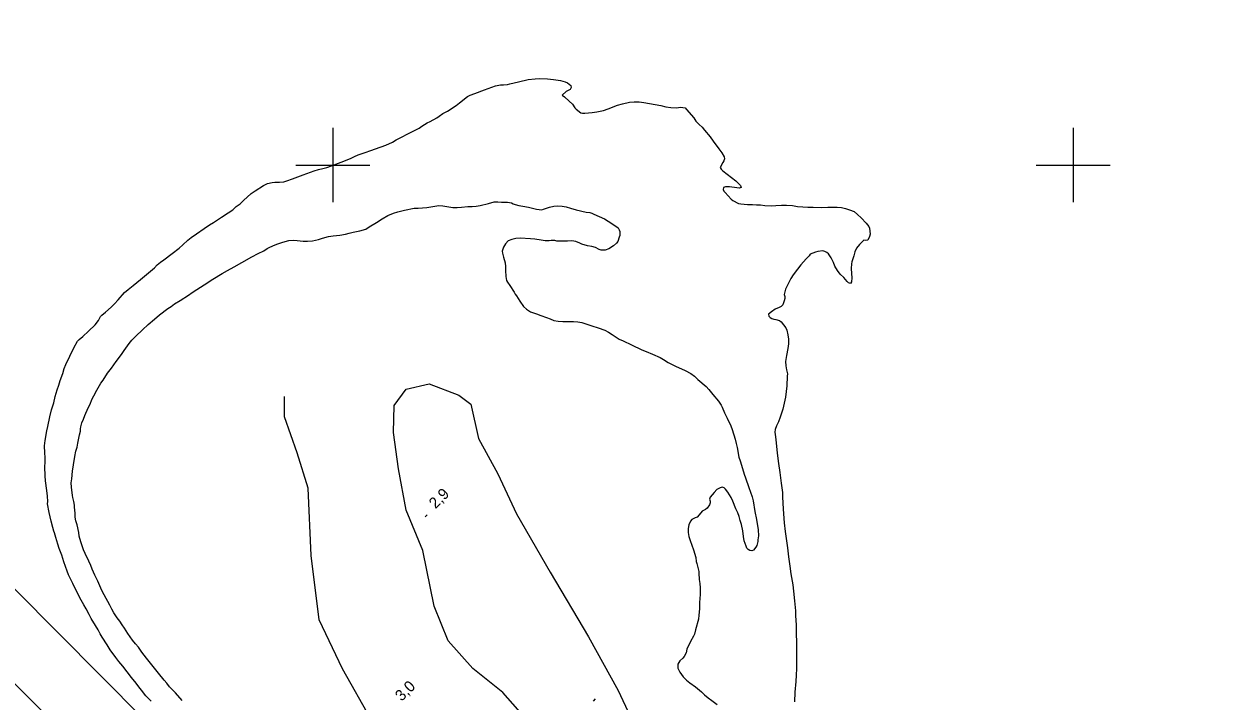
# Model space of a CAD drawing. Extents: x 381879 to 384696, y 5564785 to 5567594.
# Drawn here: x 382116.5 to 382438.6, y 5565455.1 to 5565638.1 of the extents above; entities that cross this region are included whole.
import ezdxf

# ---------------------------------------------------------------- set-up
doc = ezdxf.new("R2010")
doc.units = 0
for name, color, linetype in [('Niveau 2', 7, 'Continuous'), ('Niveau 22', 7, 'Continuous'), ('Niveau 3', 7, 'Continuous'), ('Niveau 4', 7, 'Continuous'), ('Niveau 60', 7, 'Continuous'), ('Niveau 61', 7, 'Continuous')]:
    doc.layers.add(name, color=color, linetype=linetype)

msp = doc.modelspace()

# ---------------------------------------------------------------- linework, layer by layer
at = {"layer": 'Niveau 2'}
for points in [[(382130.91, 5565523.8), (382131.1, 5565524.86), (382131.56, 5565527.09), (382131.86, 5565528.1), (382131.82, 5565528.68), (382131.89, 5565529.25), (382132.14, 5565530.3), (382132.62, 5565531.32), (382133.01, 5565532.34), (382133.85, 5565534.4), (382134.4, 5565535.42), (382134.86, 5565536.6), (382135.45, 5565537.61), (382136.27, 5565539.19), (382137.29, 5565541.05), (382137.9, 5565541.89), (382139.15, 5565543.73), (382140.19, 5565545.12), (382141.49, 5565546.92), (382142.92, 5565548.79), (382143.64, 5565549.9), (382144.94, 5565551.78), (382145.65, 5565552.63), (382146.81, 5565553.8), (382148.54, 5565555.47), (382150.09, 5565556.91), (382151.77, 5565558.39), (382153.2, 5565559.51), (382155.4, 5565561.25), (382156.32, 5565561.81), (382157.25, 5565562.48), (382158.71, 5565563.36), (382161.03, 5565564.81), (382161.97, 5565565.52), (382163.25, 5565566.39), (382165.2, 5565567.66), (382167.54, 5565569.12), (382170.08, 5565570.71), (382171.52, 5565571.54), (382173.36, 5565572.53), (382175.42, 5565573.7), (382178.13, 5565575.22), (382179.82, 5565576.11), (382181.31, 5565576.83), (382182.22, 5565577.46), (382182.74, 5565577.74), (382183.74, 5565578.19), (382184.83, 5565578.58), (382186.52, 5565579.13), (382188.07, 5565579.58), (382189.28, 5565579.67), (382190.34, 5565579.61), (382191.98, 5565579.43), (382193.16, 5565579.39), (382194.46, 5565579.5), (382196.1, 5565579.85), (382197.19, 5565580.25), (382198.83, 5565580.72), (382200.08, 5565580.9), (382201.86, 5565581.06), (382203.36, 5565581.31), (382204.37, 5565581.61), (382205.48, 5565581.84), (382207.3, 5565582.17), (382208.87, 5565582.67), (382209.84, 5565583.27), (382211.82, 5565584.43), (382213.34, 5565585.43), (382214.87, 5565586.32), (382216.38, 5565587.03), (382217.54, 5565587.35), (382219.31, 5565587.77), (382221.93, 5565588.31), (382223.04, 5565588.34), (382225.35, 5565588.49), (382226.45, 5565588.71), (382228.62, 5565589.04), (382229.72, 5565588.99), (382230.82, 5565588.76), (382232.43, 5565588.52), (382233.59, 5565588.52), (382234.7, 5565588.65), (382236.46, 5565588.81), (382237.58, 5565588.8), (382238.72, 5565588.88), (382239.76, 5565589.1), (382241.99, 5565589.62), (382243.57, 5565590.07), (382244.56, 5565590.09), (382245.58, 5565589.98), (382247.21, 5565589.97), (382248.21, 5565589.77), (382248.67, 5565589.52), (382249.21, 5565589.34), (382250.25, 5565589.08), (382251.31, 5565588.91), (382252.87, 5565588.57), (382254.96, 5565588.07), (382256.43, 5565587.91), (382256.92, 5565588.09), (382258.55, 5565588.62)], [(382258.55, 5565588.62), (382259.68, 5565588.88), (382260.76, 5565588.94), (382261.89, 5565588.88), (382263.01, 5565588.71), (382264.19, 5565588.33), (382265.71, 5565587.9), (382268.4, 5565587.23), (382269.45, 5565587.13), (382269.96, 5565586.98), (382270.45, 5565586.73), (382271.97, 5565586.13), (382273.39, 5565585.44), (382274.34, 5565584.85), (382276.15, 5565583.65), (382277.05, 5565582.98), (382277.32, 5565582.52), (382277.49, 5565581.99), (382277.52, 5565580.97), (382277.37, 5565580.46), (382276.97, 5565579.36), (382276.58, 5565578.86), (382275.81, 5565578.19), (382274.54, 5565577.34), (382273.51, 5565576.97), (382272.5, 5565576.98), (382271.94, 5565577.18), (382270.95, 5565577.67), (382269.92, 5565577.98), (382268.76, 5565578.17), (382267.23, 5565578.57), (382266.73, 5565578.89), (382265.61, 5565579.34), (382264.52, 5565579.47), (382263.4, 5565579.43), (382260.47, 5565579.42), (382259.97, 5565579.62), (382258.98, 5565579.62), (382258.45, 5565579.54), (382257.38, 5565579.52), (382256.26, 5565579.67), (382254.51, 5565579.99), (382253.34, 5565580.07), (382250.55, 5565580.24), (382249.44, 5565580.15), (382248.35, 5565579.86), (382247.32, 5565579.48), (382246.67, 5565578.72), (382246.1, 5565577.76), (382245.74, 5565576.73), (382245.81, 5565576.21), (382246.07, 5565575.12), (382246.51, 5565573.61), (382246.63, 5565572.55), (382246.59, 5565571.53), (382246.68, 5565569.84), (382246.92, 5565568.83), (382247.14, 5565568.38), (382247.79, 5565567.46), (382249, 5565565.68), (382249.22, 5565565.13), (382249.58, 5565564.65), (382250.48, 5565563.19), (382251.49, 5565561.73), (382252.31, 5565561.01), (382253.34, 5565560.37), (382253.92, 5565560.15), (382255.02, 5565559.81), (382256.14, 5565559.34), (382257.74, 5565558.81), (382258.71, 5565558.4), (382259.71, 5565558.01), (382260.88, 5565557.84), (382262.07, 5565557.74), (382263.83, 5565557.68), (382264.99, 5565557.73), (382266.12, 5565557.64), (382267.24, 5565557.45), (382268.3, 5565557.11), (382269.94, 5565556.51), (382271.66, 5565555.98), (382273.42, 5565555.37), (382274.47, 5565554.83), (382275.4, 5565554.2), (382277.37, 5565552.93), (382278.4, 5565552.46), (382280.64, 5565551.4), (382283.46, 5565550.06), (382284.64, 5565549.62), (382286.32, 5565548.92), (382288.45, 5565547.99), (382289.33, 5565547.48), (382290.61, 5565546.65), (382291.64, 5565546.09), (382292.59, 5565545.67), (382295.19, 5565544.46), (382296.7, 5565543.67), (382297.67, 5565542.94), (382298.6, 5565542.09), (382300.8, 5565540.12), (382301.54, 5565539.33)], [(382301.54, 5565539.33), (382302.62, 5565538), (382304.17, 5565536.17), (382304.89, 5565535.15), (382305.12, 5565534.58), (382305.8, 5565533.07), (382306.51, 5565531.62), (382307.46, 5565529.53), (382307.83, 5565528.51), (382308.69, 5565525.92), (382308.98, 5565524.79), (382309.17, 5565523.72), (382309.69, 5565521.09), (382309.98, 5565520.11), (382310.64, 5565518.04), (382311.07, 5565516.49), (382311.44, 5565515.46), (382312.38, 5565512.89), (382313.3, 5565510.34), (382313.49, 5565509.27), (382313.98, 5565506.4), (382314.42, 5565504.18), (382314.87, 5565501.45), (382314.94, 5565499.8), (382314.77, 5565498.77), (382314.82, 5565498.24), (382314.55, 5565497.24), (382314.25, 5565496.77), (382313.63, 5565495.93), (382313.16, 5565495.72), (382312.62, 5565495.83), (382312.18, 5565496.09), (382311.84, 5565496.5), (382311.65, 5565497), (382311.14, 5565498.49), (382310.92, 5565499.6), (382310.73, 5565501.17), (382310.35, 5565502.83), (382310.01, 5565503.92), (382309.75, 5565505.02), (382309.38, 5565506.03), (382308.89, 5565507.13), (382308.05, 5565509.16), (382307.55, 5565510.14), (382306.69, 5565511.59), (382306.06, 5565512.45), (382305.67, 5565512.8), (382305.17, 5565512.93), (382304.65, 5565512.75), (382303.7, 5565512.29), (382302.95, 5565511.52), (382301.89, 5565510.22), (382301.76, 5565509.7), (382301.92, 5565509.22), (382301.91, 5565508.7), (382301.7, 5565508.18), (382301.13, 5565507.28), (382300.68, 5565506.97), (382299.77, 5565506.47), (382299.43, 5565506.04), (382298.38, 5565504.82), (382297.9, 5565504.64), (382296.93, 5565504.21), (382296.62, 5565503.79), (382296.17, 5565502.8), (382296, 5565501.81), (382295.96, 5565500.75), (382296.19, 5565499.63), (382296.55, 5565498.54), (382297.4, 5565496), (382298, 5565493.92), (382298.14, 5565492.84), (382298.29, 5565492.32), (382298.84, 5565490.2), (382298.87, 5565489.68), (382298.91, 5565487.99), (382299.09, 5565486.92), (382299.19, 5565485.79), (382299.2, 5565483.98), (382299.08, 5565482.9), (382299.07, 5565481.8), (382299, 5565480.11), (382298.85, 5565478.41), (382298.78, 5565477.26)], [(382159.27, 5565455.29), (382157.45, 5565457.35), (382155.87, 5565459.05), (382155.17, 5565459.99), (382154.4, 5565460.84), (382152.87, 5565462.68), (382151.08, 5565464.97), (382149.65, 5565466.74), (382148.37, 5565468.4), (382147.45, 5565469.7), (382146.66, 5565470.62), (382145.9, 5565471.64), (382144.61, 5565473.46), (382143.74, 5565474.88), (382143.09, 5565475.76), (382142.45, 5565476.75), (382141.73, 5565477.67), (382140.8, 5565479.03), (382140.26, 5565480.02), (382139.76, 5565481.08), (382139.17, 5565482.08), (382137.74, 5565484.64), (382137.33, 5565485.69), (382136.5, 5565487.59), (382135.68, 5565489.2), (382134.94, 5565490.83), (382134.57, 5565491.84), (382134.03, 5565492.93), (382133.04, 5565495.02), (382132.66, 5565496.07), (382131.94, 5565498.17), (382131.5, 5565499.73), (382131.35, 5565500.75), (382130.94, 5565502.82), (382130.6, 5565503.84), (382130.38, 5565504.88), (382130.36, 5565505.95), (382130.17, 5565507.53), (382130.17, 5565508.08), (382130.03, 5565509.11), (382129.73, 5565510.17), (382129.67, 5565510.74), (382129.39, 5565513), (382129.34, 5565514.11), (382129.45, 5565515.24), (382129.7, 5565517.31), (382129.97, 5565519.01), (382130.27, 5565521.2), (382130.57, 5565522.73), (382130.91, 5565523.8)], [(382298.78, 5565477.26), (382297.96, 5565474.45), (382297.7, 5565473.27), (382297.44, 5565472.73), (382296.62, 5565471.22), (382295.62, 5565469.19), (382295.39, 5565468.21), (382294.9, 5565467.18), (382294.52, 5565466.74), (382293.71, 5565466.02), (382293.18, 5565465.12), (382293.14, 5565464.58), (382293.22, 5565464.03), (382293.43, 5565463.5), (382293.74, 5565463.02), (382294.66, 5565461.69), (382295.51, 5565460.83), (382296.43, 5565460.08), (382297.96, 5565458.97), (382299.57, 5565457.66), (382300.36, 5565456.86), (382301.33, 5565456.02), (382302.38, 5565455.31), (382303.79, 5565454.2)]]:
    msp.add_lwpolyline(points, dxfattribs=at)
at = {"layer": 'Niveau 22'}
for points in [[(382253.31, 5565449.12), (382245.9, 5565457.45), (382237.81, 5565463.94), (382231.16, 5565471.45), (382227.33, 5565480.81), (382224.26, 5565495.86), (382219.76, 5565506.7), (382217.73, 5565517.9), (382216.36, 5565527.73), (382216.57, 5565535.04), (382219.77, 5565539.46), (382225.99, 5565540.87), (382234.01, 5565537.83), (382237.3, 5565535.36)], [(382210.41, 5565450.05), (382202.61, 5565463.87), (382196.31, 5565477.16), (382194.11, 5565494.49), (382193.3, 5565512.67), (382190.33, 5565522.23), (382186.9, 5565531.95), (382186.9, 5565537.44)], [(382237.3, 5565535.36), (382239.31, 5565526.14), (382244.54, 5565516.57), (382249.6, 5565505.77), (382258.65, 5565490.02), (382269.07, 5565472.55), (382277.03, 5565457.99), (382283.57, 5565444.11), (382288.48, 5565435.6), (382298.71, 5565424.74), (382312.05, 5565413.36), (382327.25, 5565399.78), (382338.53, 5565390.13), (382349.13, 5565379.71), (382357.88, 5565369.66), (382364.26, 5565357.44), (382374.61, 5565345.91), (382383.36, 5565338.66), (382392.15, 5565330.52), (382402.06, 5565320.89), (382411.75, 5565307.15), (382418.26, 5565298.9), (382427.75, 5565289.33), (382436.26, 5565282.09)]]:
    msp.add_lwpolyline(points, dxfattribs=at)
at = {"layer": 'Niveau 3'}
for p, q in [((382224.92, 5565504.93), (382225.49, 5565505.5)), ((382270.41, 5565455.16), (382270.98, 5565455.73))]:
    msp.add_line(p, q, dxfattribs=at)
at = {"layer": 'Niveau 4'}
for points in [[(382228.7, 5565613.23), (382229.69, 5565613.93), (382230.92, 5565614.58), (382233.28, 5565616.04), (382234.18, 5565616.76), (382236.39, 5565618.52), (382237.04, 5565618.87), (382238.32, 5565619.33), (382240.93, 5565620.29), (382243.88, 5565621.36), (382245.26, 5565621.69), (382246.1, 5565621.69), (382247.13, 5565621.77), (382247.78, 5565621.94), (382250.11, 5565622.5), (382252.77, 5565623.08), (382254.6, 5565623.29), (382255.92, 5565623.34), (382257.96, 5565623.31), (382259.6, 5565623.12), (382261.45, 5565622.82), (382262.72, 5565622.5), (382263.33, 5565622.22), (382264.25, 5565621.46), (382264.33, 5565620.92), (382264.11, 5565620.39), (382263.59, 5565620.09), (382263.01, 5565619.89), (382261.96, 5565618.85), (382262.53, 5565618.39), (382263.83, 5565617.28), (382264.73, 5565616.4), (382265.32, 5565615.49), (382265.68, 5565615.13), (382266.98, 5565614.08), (382267.47, 5565613.98), (382268.03, 5565614.04), (382270.08, 5565614.17), (382271.28, 5565614.37), (382273.1, 5565614.76), (382274.36, 5565615.21), (382276.88, 5565616.13), (382278.2, 5565616.49), (382280.08, 5565616.94), (382281.4, 5565617.11), (382282.74, 5565617.09), (382284.03, 5565616.91), (382285.5, 5565616.63), (382288.61, 5565616.07), (382289.9, 5565615.74), (382291.25, 5565615.57), (382292.84, 5565615.48), (382293.94, 5565615.63), (382295.19, 5565615.41), (382295.56, 5565614.98), (382297.46, 5565612.71), (382298.06, 5565611.82), (382298.9, 5565610.95), (382299.76, 5565610.21), (382300.42, 5565609.38), (382301.94, 5565607.57), (382302.74, 5565606.48), (382304.28, 5565604.35), (382305.1, 5565603.32), (382305.69, 5565602.21), (382305.75, 5565601.69), (382305.6, 5565601.13), (382305.29, 5565600.71), (382304.62, 5565599.29), (382304.89, 5565598.85), (382305.29, 5565598.45), (382306.46, 5565597.49), (382308.85, 5565595.68), (382310.1, 5565594.44), (382310.3, 5565593.89), (382309.74, 5565593.77), (382309.08, 5565593.86), (382307.13, 5565594.08), (382306.05, 5565594.09), (382305.54, 5565593.93), (382305.41, 5565593.42), (382305.64, 5565592.95), (382305.98, 5565592.53), (382307.54, 5565590.76), (382308.02, 5565590.42), (382309.55, 5565589.6), (382310.21, 5565589.49), (382312, 5565589.37), (382313.32, 5565589.36), (382314.45, 5565589.26), (382315.54, 5565589.24), (382316.7, 5565589.07), (382318.52, 5565588.97), (382319.63, 5565589.09), (382321.18, 5565589.16), (382322.51, 5565589.15), (382324.19, 5565589.06), (382325.52, 5565588.83), (382326.91, 5565588.67), (382328.27, 5565588.59), (382329.73, 5565588.61)], [(382124.66, 5565501.04), (382124.34, 5565502.1), (382123.93, 5565503.77), (382123.4, 5565506.1), (382122.94, 5565508.45), (382122.95, 5565509.11), (382122.89, 5565510.57), (382122.68, 5565512.05), (382122.33, 5565514.67), (382122.26, 5565516), (382122.17, 5565518.48), (382122.28, 5565519.71), (382122.27, 5565520.93), (382122.16, 5565522.24), (382122.11, 5565524.16), (382122.3, 5565525.55), (382122.72, 5565528.16), (382123, 5565529.33), (382123.56, 5565531.97), (382124.03, 5565533.87), (382124.59, 5565535.73), (382124.97, 5565537.46), (382125.49, 5565539.25), (382125.95, 5565540.49), (382126.35, 5565541.75), (382127.04, 5565543.69), (382127.39, 5565545.03), (382127.9, 5565546.11), (382128.92, 5565548.37), (382130.04, 5565550.6), (382131.05, 5565552.41), (382131.49, 5565552.84), (382132.49, 5565553.71), (382133.98, 5565555.07), (382135.77, 5565556.78), (382136.64, 5565557.97), (382137.2, 5565559.05), (382137.57, 5565559.4), (382138.59, 5565560.25), (382140.14, 5565561.6), (382141.03, 5565562.53), (382141.96, 5565563.6), (382143.7, 5565565.55), (382144.68, 5565566.4), (382146.04, 5565567.44), (382148.02, 5565569.06), (382150.18, 5565570.84), (382151.81, 5565572.25), (382152.53, 5565573.01), (382153.41, 5565573.75), (382154.31, 5565574.4), (382156.59, 5565576.07), (382158.46, 5565577.5), (382159.43, 5565578.44), (382160.78, 5565579.68), (382161.7, 5565580.43), (382163.14, 5565581.38), (382165.27, 5565582.82), (382166.7, 5565583.85), (382167.73, 5565584.5), (382169.89, 5565585.93), (382171.74, 5565587.06), (382172.95, 5565587.88), (382173.91, 5565588.78), (382174.94, 5565589.53), (382175.83, 5565590.39), (382177.92, 5565592.34), (382178.98, 5565593.04), (382181.21, 5565594.45), (382182.31, 5565594.96), (382183.61, 5565595.31), (382184.31, 5565595.36), (382185.57, 5565595.35), (382186.78, 5565595.43), (382187.52, 5565595.68), (382189.07, 5565596.28), (382191.98, 5565597.37), (382194.92, 5565598.44), (382196.13, 5565598.8), (382197.31, 5565599.02), (382198.33, 5565599.34), (382199.63, 5565599.82), (382202.24, 5565600.78), (382204.77, 5565601.73), (382205.81, 5565602.29), (382206.82, 5565602.71), (382208.72, 5565603.4), (382210.29, 5565603.89), (382211.52, 5565604.34), (382214.28, 5565605.39), (382216.09, 5565606.16), (382217.11, 5565606.79), (382218.19, 5565607.38), (382220.56, 5565608.61), (382222.22, 5565609.39), (382223.33, 5565609.99), (382224.01, 5565610.49), (382225.48, 5565611.4), (382226.25, 5565611.75), (382228.08, 5565612.73), (382228.7, 5565613.23)], [(382329.73, 5565588.61), (382331.86, 5565588.56), (382333.67, 5565588.57), (382336.21, 5565588.61), (382337.37, 5565588.55), (382338.49, 5565588.29), (382339.57, 5565587.93), (382340.8, 5565587.42), (382341.75, 5565586.67), (382342.69, 5565585.76), (382344.09, 5565584.3), (382344.79, 5565583.38), (382344.98, 5565582.9), (382345.11, 5565581.27), (382344.93, 5565580.65), (382344.46, 5565579.7), (382343.96, 5565579.58), (382343.42, 5565579.65), (382343.02, 5565579.31), (382342.21, 5565578.5), (382341.46, 5565577.57), (382340.97, 5565576.57), (382340.69, 5565575.47), (382340.19, 5565573.84), (382340.11, 5565573.29), (382340.03, 5565572.01), (382340.06, 5565570.71), (382340.18, 5565569.53), (382340.08, 5565568.47), (382339.81, 5565568.01), (382339.27, 5565568.14), (382338.92, 5565568.52), (382338.03, 5565569.58), (382337.04, 5565570.55), (382336.33, 5565571.5), (382335.63, 5565572.65), (382335.24, 5565573.68), (382334.63, 5565574.91), (382333.88, 5565575.96), (382333.4, 5565576.39), (382332.91, 5565576.67), (382332.33, 5565576.79), (382331.03, 5565576.67), (382330.41, 5565576.45), (382328.93, 5565575.87), (382328.61, 5565575.45), (382327.84, 5565574.63), (382326.4, 5565573), (382325.51, 5565571.9), (382324.31, 5565570.35), (382323.67, 5565569.3), (382323.11, 5565568.1), (382322.28, 5565566.48), (382321.91, 5565564.99), (382322.09, 5565564.47), (382322.09, 5565563.96), (382321.94, 5565563.32), (382321.52, 5565562.23), (382321.09, 5565561.78), (382320.55, 5565561.49), (382319.48, 5565561.04), (382318.46, 5565560.37), (382317.66, 5565559.69), (382317.77, 5565559.16), (382318.13, 5565558.79), (382318.57, 5565558.49), (382319.09, 5565558.31), (382319.64, 5565558.28), (382320.62, 5565557.96), (382321.07, 5565557.65)], [(382321.07, 5565557.65), (382322.36, 5565556), (382322.6, 5565555.34), (382322.87, 5565554.08), (382323.04, 5565552.92), (382323.04, 5565551.68), (382322.85, 5565550.44), (382322.49, 5565548.54), (382322.25, 5565546.88), (382322.31, 5565545.76), (382322.57, 5565544.65), (382322.77, 5565543.58), (382322.73, 5565542.91), (382322.61, 5565540.32), (382322.47, 5565538.79), (382322.25, 5565537.24), (382321.94, 5565535.69), (382321.51, 5565534.06), (382320.8, 5565531.84), (382320.35, 5565530.65), (382319.86, 5565529.56), (382319.51, 5565528.5), (382319.42, 5565527.8), (382319.52, 5565526.55), (382319.7, 5565524.94), (382320.04, 5565522.14), (382320.38, 5565519.31), (382320.71, 5565516.89), (382321.09, 5565514.08), (382321.41, 5565511.48), (382321.48, 5565510.24), (382321.65, 5565507.11), (382321.78, 5565504.52), (382321.93, 5565503.34), (382322.17, 5565500.96), (382322.42, 5565499.05), (382322.78, 5565496.59), (382323.08, 5565494.17), (382323.41, 5565491.59), (382323.73, 5565489.57), (382324.22, 5565486.6), (382324.42, 5565484.85), (382324.69, 5565482.22), (382324.93, 5565479.59), (382324.97, 5565478.32), (382325.1, 5565475.66), (382325.15, 5565473.47), (382325.22, 5565470.89), (382325.21, 5565468.96), (382325.2, 5565466.38), (382325.23, 5565463.97), (382325.18, 5565462.17), (382325.06, 5565460.44), (382324.81, 5565457.53), (382324.65, 5565454.92)], [(382132.04, 5565482.39), (382130.67, 5565485.04), (382129.75, 5565486.92), (382128.59, 5565489.29), (382128.24, 5565490.28), (382127.32, 5565492.83), (382126.75, 5565494.55), (382126.07, 5565496.42), (382125.73, 5565497.57), (382125.14, 5565499.36), (382124.79, 5565500.64), (382124.66, 5565501.04)], [(382150.94, 5565455.1), (382149.49, 5565456.62), (382148.26, 5565458.07), (382147.59, 5565459.04), (382146.84, 5565459.97), (382145.61, 5565461.58), (382144.39, 5565463.08), (382143.25, 5565464.58), (382142.13, 5565465.9), (382141.34, 5565466.97), (382139.81, 5565469.01), (382139.01, 5565470.32), (382137.68, 5565472.42), (382137.15, 5565473.29), (382136.56, 5565474.44), (382135.87, 5565475.55), (382134.74, 5565477.44), (382134.18, 5565478.54), (382133.33, 5565480.11), (382132.69, 5565481.15), (382132.04, 5565482.39)]]:
    msp.add_lwpolyline(points, dxfattribs=at)
at = {"layer": 'Niveau 60'}
for points in [[(381881.93, 5565693.86), (383794.53, 5567591.15), (384693.12, 5566685.31), (382780.52, 5564788.02)], [(383653.8, 5566971.92), (383426.67, 5567200.87), (383197.47, 5566973.49), (381907.4, 5565693.71), (382780.65, 5564813.45), (384299.92, 5566320.61)]]:
    msp.add_lwpolyline(points, close=True, dxfattribs=at)
at = {"layer": 'Niveau 61'}
for points in [[(382200, 5565610), (382200, 5565600), (382200, 5565590)], [(382400, 5565610), (382400, 5565600), (382400, 5565590)], [(382190, 5565600), (382200, 5565600), (382210, 5565600)], [(382390, 5565600), (382400, 5565600), (382410, 5565600)]]:
    msp.add_lwpolyline(points, dxfattribs=at)

# ---------------------------------------------------------------- texts
at = {"layer": 'Niveau 3'}
for s, p in [('2,9', (382227.72, 5565506.95)), ('3,0', (382218.57, 5565454.95))]:
    msp.add_text(s, height=3, rotation=44.7717, dxfattribs=at).set_placement(p)

doc.saveas('drawing.dxf')
